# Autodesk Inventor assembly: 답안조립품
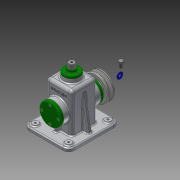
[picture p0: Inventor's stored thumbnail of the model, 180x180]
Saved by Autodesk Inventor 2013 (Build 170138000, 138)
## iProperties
Created: 2016-01
Part Number: 답안조립품
Document SubType Name: Assembly
Designer: Administrator
Author: Administrator
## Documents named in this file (19)
- C:\Users\Administrator\Desktop\460127V1011\답안조립품.iam
- C:\Users\Administrator\Desktop\460127V1011\1본체.ipt
- C:\Users\Administrator\Desktop\460127V1011\V-벨트풀리.ipt
- C:\Users\Administrator\Desktop\460127V1011\고정핀.ipt
- C:\Users\Administrator\Desktop\460127V1011\뒤커버.ipt
- C:\Users\Administrator\Desktop\460127V1011\링크.ipt
- C:\Users\Administrator\Desktop\460127V1011\멈춤링 6 x 5.ipt
- C:\Users\Administrator\Desktop\460127V1011\멈춤링 15 x 1.ipt
- C:\Users\Administrator\Desktop\460127V1011\베어링 15 x 35 x 11.ipt
- C:\Users\Administrator\Desktop\460127V1011\볼트 M3 x 8.ipt
- C:\Users\Administrator\Desktop\460127V1011\볼트 M4 x 10.ipt
- C:\Users\Administrator\Desktop\460127V1011\볼트 M6 x 12.ipt
- C:\Users\Administrator\Desktop\460127V1011\상부부시.ipt
- C:\Users\Administrator\Desktop\460127V1011\슬라이드바.ipt
- C:\Users\Administrator\Desktop\460127V1011\앞커버.ipt
- C:\Users\Administrator\Desktop\460127V1011\오일실 15 25 7.ipt
- C:\Users\Administrator\Desktop\460127V1011\와셔.ipt
- C:\Users\Administrator\Desktop\460127V1011\키 5 x 5 x 14.ipt
- C:\Users\Administrator\Desktop\460127V1011\편심축.ipt
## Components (16 placed, 6 different names)
1. 1본체:1
2. V-벨트풀리:1 — 각도:2
3. 고정핀:1
4. ISO 4018 M6 x 12:1
5. ISO 4762 M4 x 10:2
6. ISO 4762 M4 x 10:3
7. ISO 4762 M4 x 10:4
8. ISO 4762 M4 x 10:5
9. ISO 4762 M4 x 10:1
10. ISO 4762 M4 x 10:6
11. ISO 4762 M4 x 10:7
12. ISO 4762 M4 x 10:8
13. ISO 4762 M3 x 8:1
14. ISO 4762 M3 x 8:2
15. ISO 4762 M3 x 8:3
16. ISO 4762 M3 x 8:4
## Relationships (1: Angle 1)
- 각도:2 [Angle]: V-벨트풀리:1
